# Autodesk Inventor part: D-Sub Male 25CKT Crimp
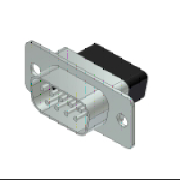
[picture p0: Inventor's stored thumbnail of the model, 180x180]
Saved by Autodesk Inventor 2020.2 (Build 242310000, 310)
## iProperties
Manager: www.cadconsulting.pl
Company: Fabian Stasiak CAD Consulting
IsCustomPart: 0
GlobalPropertyList: <PropertyList/>
Created: 2014-02
Part Number: D-Sub Male 25CKT Crimp
Material: Ogólny
Description: Wtyczka, złącze D-Sub
Document SubType Name: Modeling
Designer: F.Stasiak
Language: pl-PL
Size Designation: D-Sub Male Crimp 25CKT
Categories: <MemberInstance><Categories><Category DisplayName="Kable i wiązki przewodów" InternalName="e4a7e005-5e42-4d16-b293-125e7f0d0512" Mnemonic="CABLEANDHARNESS"><Cat
Density: 1 g/cm^3
Appearance: Domyślna
Catalog Web Link: www.expertbooks.pl
Author: F.Stasiak
Subject: Zbiór ćwiczeń. Autodesk Inventor 2020. Kurs Professional
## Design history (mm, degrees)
sketch "Sketch1"
  geometry: L1 (24.943, 6.299)-(-24.943, 6.299); L2 (-24.943, -6.299)-(24.943, -6.299); L3 (26.518, -4.724)-(26.518, 4.724); L4 (-26.518, 4.724)-(-26.518, -4.724); L5 (0, 6.299)-(0, -6.299); L6 (-23.52, 0)-(23.52, 0); L7 (26.518, 4.724)-(24.943, 4.724); L8 (24.943, 4.724)-(24.943, 6.299); L9 (26.518, -4.724)-(24.943, -4.724); L10 (24.943, -4.724)-(24.943, -6.299); L11 (-24.943, 6.299)-(-24.943, 4.724); L12 (-24.943, 4.724)-(-26.518, 4.724); L13 (-26.518, -4.724)-(-24.943, -4.724); L14 (-24.943, -4.724)-(-24.943, -6.299); C1 r 1.524 at (-23.52, 0); C2 r 1.524 at (23.52, 0); A1 r 1.575 centre (24.943, 4.724) between (26.518, 4.724) and (24.943, 6.299); A2 r 1.575 centre (24.943, -4.724) between (24.943, -6.299) and (26.518, -4.724); A3 r 1.575 centre (-24.943, 4.724) between (-24.943, 6.299) and (-26.518, 4.724); A4 r 1.575 centre (-24.943, -4.724) between (-26.518, -4.724) and (-24.943, -6.299); 7 further points
  constraints: 28 end point, 8 point on circle, 6 centre point, 6 midpoint, 5 perpendicular, 4 horizontal alignment, 4 vertical alignment, 3 equal radius, 3 parallel, 1 coincident
  dimensions: "d124" = 53.0352 distance between parallel lines of L3 L4 (derived); "d125" = 12.5984 distance between parallel lines of L2 L1; "d126" = 1.5748 radius of A1; "d134" = 3.048 diameter of C1; "d135" = 47.0408 distance of L6.start L6.end (derived)
extrude "Wyciągnięcie1" new body sketch "Sketch1" stored distance "d4" = 0.762; taper "d5" = 0 deg
sketch "Sketch2"
  geometry: L1 (-24.943, 6.299)-(24.943, 6.299) reference; L2 (24.943, -6.299)-(-24.943, -6.299) reference; L3 (-16.153, -3.95)-(16.153, -3.95); L4 (16.65, 3.95)-(-16.65, 3.95); L5 (-19.151, 0.969)-(-18.654, -1.851); L6 (18.654, -1.851)-(19.151, 0.969); L7 (0, 3.95)-(0, -3.95); L8 (-19.19, 6.299)-(-19.19, -6.299); L9 (19.19, 6.299)-(19.19, -6.299); L10 (26.518, 4.724)-(26.518, -4.724) reference; L11 (-16.65, 4.356)-(16.65, 4.356); L12 (-16.153, -4.356)-(16.153, -4.356); L13 (-19.551, 0.898)-(-19.054, -1.921); L14 (19.551, 0.898)-(19.054, -1.921); A1 r 2.54 centre (-16.65, 1.41) between (-16.65, 3.95) and (-19.151, 0.969); A2 r 2.54 centre (-16.153, -1.41) between (-18.654, -1.851) and (-16.153, -3.95); A3 r 2.54 centre (16.153, -1.41) between (16.153, -3.95) and (18.654, -1.851); A4 r 2.54 centre (16.65, 1.41) between (19.151, 0.969) and (16.65, 3.95); A5 r 2.946 centre (-16.65, 1.41) between (-16.65, 4.356) and (-19.551, 0.898); A6 r 2.946 centre (16.153, -1.41) between (16.153, -4.356) and (19.054, -1.921); A7 r 2.946 centre (16.65, 1.41) between (19.551, 0.898) and (16.65, 4.356); A8 r 2.946 centre (-16.153, -1.41) between (-19.054, -1.921) and (-16.153, -4.356); 7 further points
  constraints: 22 end point, 16 point on circle, 8 centre point, 7 tangent, 6 midpoint, 4 coincident, 4 point on line, 3 equal radius, 3 parallel, 3 perpendicular, 2 vertical alignment, 1 horizontal alignment
  dimensions: "d127" = 2.54 radius of A4; "d129" = 7.8994 distance between parallel lines of L3 L4; "d131" = 10 deg angle of L7 L5; "d132" = 10 deg angle of L6 L7; "d133" = 38.3794 distance between parallel lines of L9 L8 (derived); "d198" = 0.49714 horizontal distance of A2.centre A1.centre; "d199" = 2.8194 vertical distance of A2.centre A1.centre; "d200" = 0.49714 horizontal distance of A3.centre A4.centre; "d201" = 2.8194 vertical distance of A3.centre A4.centre; "d292" = 0.4064 radial gap between concentric circles of A1 A5; "d293" = 0.4064 distance between parallel lines of L11 L4 (derived); "d294" = 0.4064 distance between parallel lines of L3 L12 (derived)
extrude "Wyciągnięcie2" join sketch "Sketch2" distance "d9" = 5.5372; taper "d10" = 0 deg
sketch "Sketch3"
  geometry: L1 (-20.61, 3.651)-(-19.226, -4.198); L2 (-17.676, -5.499)-(17.676, -5.499); L3 (19.059, 5.499)-(-19.059, 5.499); L4 (19.226, -4.198)-(20.586, 3.512); L5 (0, 5.499)-(0, -5.499); L6 (-20.634, 6.274)-(-20.634, -6.274); L7 (20.641, 6.274)-(20.641, -6.274); L8 (-24.943, 6.299)-(24.943, 6.299) reference; L9 (-26.518, -4.724)-(-26.518, 4.724) reference; L10 (24.943, -6.299)-(-24.943, -6.299) reference; L11 (-19.059, 5.499)-(-19.059, 3.924); L12 (-19.059, 3.924)-(-20.61, 3.651); L13 (-19.226, -4.198)-(-17.676, -3.924); L14 (-17.676, -3.924)-(-17.676, -5.499); L15 (17.676, -3.924)-(17.676, -5.499); L16 (17.676, -3.924)-(19.226, -4.198); L17 (19.059, 5.499)-(19.066, 3.924); L18 (19.066, 3.924)-(20.586, 3.512); L19 (26.518, 4.724)-(26.518, -4.724) reference; A1 r 1.575 centre (-17.676, -3.924) between (-19.226, -4.198) and (-17.676, -5.499); A2 r 1.575 centre (-19.059, 3.924) between (-19.059, 5.499) and (-20.61, 3.651); A3 r 1.575 centre (17.676, -3.924) between (17.676, -5.499) and (19.226, -4.198); A4 r 1.575 centre (19.066, 3.924) between (20.586, 3.512) and (19.059, 5.499); 5 further points
  constraints: 30 end point, 8 point on circle, 5 midpoint, 4 centre point, 4 parallel, 3 equal radius, 3 perpendicular, 2 horizontal alignment, 2 tangent, 2 vertical alignment
  dimensions: "d114" = 10.9982 distance between parallel lines of L2 L3; "d119" = 1.5748 radius of A4; "d120" = 10 deg angle of L5 L1; "d121" = 10 deg angle of L4 L5; "d122" = 41.275 distance between parallel lines of L7 L6 (derived); "d204" = 90 deg angle of L3 L11; "d205" = 100 deg angle of L11 L12; "d206" = 90 deg angle of L2 L14 (derived); "d207" = 80 deg angle of L14 L13 (derived); "d208" = 90 deg angle of L2 L15 (derived); "d209" = 80 deg angle of L16 L15 (derived); "d210" = 105.42 deg angle of L17 L18 (derived); "d211" = 90.2379 deg angle of L3 L17 (derived); "d295" = 1.38392 horizontal distance of L13.end L11.end; "d296" = 1.39046 horizontal distance of L15.start L17.end
extrude "Wyciągnięcie3" join sketch "Sketch3" distance "d14" = 3.937; taper "d15" = 0 deg
sketch "Sketch4"
  geometry: L1 (-19.059, 5.499)-(19.059, 5.499) reference; L2 (18.046, -2.574)-(18.879, 2.15); L3 (-16.845, -3.581)-(16.845, -3.581); L4 (17.678, 3.581)-(-17.678, 3.581); L5 (-18.879, 2.15)-(-18.046, -2.574); L6 (0, 3.581)-(0, -3.581); L7 (26.518, 4.724)-(26.518, -4.724) reference; L8 (-24.943, 6.299)-(24.943, 6.299) reference; L9 (-26.518, -4.724)-(-26.518, 4.724) reference; L10 (24.943, -6.299)-(-24.943, -6.299) reference; L11 (-18.898, 6.299)-(-18.898, -6.299); L12 (18.898, 6.299)-(18.898, -6.299); L13 (-19.226, -4.198)-(-20.61, 3.651) reference; L14 (17.676, -5.499)-(-17.676, -5.499) reference; L15 (-17.678, 2.362)-(-17.678, 3.581); L16 (-17.678, 2.362)-(-18.879, 2.15); L17 (-16.845, -2.362)-(-16.845, -3.581); L18 (-16.845, -2.362)-(-18.046, -2.574); L19 (16.845, -2.362)-(18.046, -2.574); L20 (16.845, -2.362)-(16.845, -3.581); L21 (17.678, 3.581)-(17.678, 2.362); L22 (17.678, 2.362)-(18.879, 2.15); C1 r 1.524 at (-23.52, 0) reference; C2 r 1.524 at (23.52, 0) reference; A1 r 1.219 centre (16.845, -2.362) between (16.845, -3.581) and (18.046, -2.574); A2 r 1.219 centre (17.678, 2.362) between (18.879, 2.15) and (17.678, 3.581); A3 r 1.219 centre (-16.845, -2.362) between (-18.046, -2.574) and (-16.845, -3.581); A4 r 1.219 centre (-17.678, 2.362) between (-17.678, 3.581) and (-18.879, 2.15); A5 r 1.575 centre (24.943, 4.724) between (26.518, 4.724) and (24.943, 6.299) reference; A6 r 1.575 centre (-24.943, 4.724) between (-24.943, 6.299) and (-26.518, 4.724) reference; A7 r 1.575 centre (-24.943, -4.724) between (-26.518, -4.724) and (-24.943, -6.299) reference; A8 r 1.575 centre (24.943, -4.724) between (24.943, -6.299) and (26.518, -4.724) reference; 3 further points
  constraints: 30 end point, 8 point on circle, 6 parallel, 5 perpendicular, 4 centre point, 4 midpoint, 4 point on line, 3 equal radius, 2 tangent, 1 horizontal alignment, 1 vertical alignment
  dimensions: "d136" = 7.1628 distance between parallel lines of L3 L4; "d137" = 1.2192 radius of A2; "d139" = 10 deg angle of L6 L5; "d140" = 10 deg angle of L2 L6; "d141" = 37.7952 distance between parallel lines of L12 L11 (derived); "d212" = 90 deg angle of L4 L15; "d213" = 100 deg angle of L16 L15 (derived); "d214" = 90 deg angle of L3 L17 (derived); "d215" = 80 deg angle of L17 L18 (derived); "d216" = 90 deg angle of L3 L20 (derived); "d217" = 80 deg angle of L19 L20; "d218" = 90 deg angle of L4 L21 (derived); "d219" = 100 deg angle of L22 L21 (derived)
extrude "Wyciągnięcie4" join sketch "Sketch4" distance "d19" = 7.1882; taper "d20" = 0 deg
sketch "Sketch14"
  geometry: L1 (16.659, 3.404)-(16.659, 2.642); L2 (16.659, 2.642)-(16.564, 2.642); L3 (16.564, 2.642)-(16.564, 3.274); L4 (16.469, 3.16)-(16.469, 3.29); L5 (16.564, 3.404)-(16.659, 3.404); L6 (16.469, 3.29)-(16.564, 3.404); L7 (16.564, 3.274)-(16.469, 3.16); C1 r 1.105 at (16.612, 1.422); C2 r 1.105 at (15.245, -1.422); A1 r 1.219 centre (16.845, -2.362) between (16.845, -3.581) and (18.046, -2.574) reference; A2 r 1.219 centre (17.678, 2.362) between (18.879, 2.15) and (17.678, 3.581) reference; 1 further point
  constraints: 14 end point, 2 centre point, 1 midpoint, 1 vertical alignment
  dimensions: "d144" = 2.2098 diameter of C1; "d162" = 2.2098 diameter of C2; "d181" = 0.09525 distance of L1.end L2.end; "d182" = 40.0062 deg angle of L3 L7; "d183" = 0.1297 distance of L4.start L4.end; "d184" = 0.09525 distance of L5.start L1.start; "d185" = 0.762 distance of L1.start L1.end; "d186" = 0.6323 distance of L2.end L3.end; "d187" = 0.14816 distance of L4.end L5.start; "d188" = 0.14816 distance of L3.end L4.start; "d189" = 40.0062 deg angle of L4 L7; "d190" = 139.994 deg angle of L4 L6; "d297" = 1.0668 horizontal distance of A2.centre C1.centre; "d298" = 0.9398 vertical distance of C1.centre A2.centre; "d299" = 1.6002 horizontal distance of A1.centre C2.centre; "d300" = 0.9398 vertical distance of A1.centre C2.centre
sketch "Sketch15"
  geometry: C1 r 0.533 at (-16.612, 1.422); C2 r 0.533 at (-15.24, -1.422); A1 r 2.54 centre (16.65, 1.41) between (19.151, 0.969) and (16.65, 3.95); A2 r 2.54 centre (16.153, -1.41) between (16.153, -3.95) and (18.654, -1.851); A3 r 2.54 centre (-16.65, 1.41) between (-16.65, 3.95) and (-19.151, 0.969) reference; A4 r 2.54 centre (-16.153, -1.41) between (-18.654, -1.851) and (-16.153, -3.95) reference
  constraints: 4 centre point, 4 point on circle, 1 equal radius
  dimensions: "d149" = 1.0668 diameter of C1; "d301" = 0.0381 horizontal distance of A3.centre C1.centre; "d302" = 0.0127 vertical distance of A3.centre C1.centre; "d303" = 0.91256 horizontal distance of A4.centre C2.centre; "d304" = 0.0127 vertical distance of A4.centre C2.centre
pattern_linear "Wzór prostokątny7" dims "d159" = 2.7432 (derived)
pattern_linear "Wzór prostokątny8" dims "d178" = 2.7432 (derived)
sketch "Sketch16"
  geometry: L1 (16.659, 2.642)-(16.564, 2.642) reference; L2 (16.564, 2.642)-(16.564, 3.274) reference; L3 (16.564, 3.274)-(16.469, 3.16) reference; L4 (16.469, 3.16)-(16.469, 3.29) reference; L5 (16.469, 3.29)-(16.564, 3.404) reference; L6 (16.564, 3.404)-(16.659, 3.404) reference; L7 (16.659, 3.404)-(16.659, 2.642) reference; L8 (16.845, -3.581)-(-16.845, -3.581) reference; L9 (18.879, 2.15)-(18.046, -2.574) reference; L10 (-17.678, 3.581)-(17.678, 3.581) reference; L11 (-18.046, -2.574)-(-18.879, 2.15) reference; L12 (16.845, -3.581)-(-16.845, -3.581) reference; L13 (18.879, 2.15)-(18.046, -2.574) reference; L14 (-17.678, 3.581)-(17.678, 3.581) reference; L15 (-18.046, -2.574)-(-18.879, 2.15) reference; A1 r 1.219 centre (-17.678, 2.362) between (-17.678, 3.581) and (-18.879, 2.15) reference; A2 r 1.219 centre (16.845, -2.362) between (16.845, -3.581) and (18.046, -2.574) reference; A3 r 1.219 centre (17.678, 2.362) between (18.879, 2.15) and (17.678, 3.581) reference; A4 r 1.219 centre (-16.845, -2.362) between (-18.046, -2.574) and (-16.845, -3.581) reference; A5 r 1.219 centre (16.845, -2.362) between (16.845, -3.581) and (18.046, -2.574) reference; A6 r 1.219 centre (17.678, 2.362) between (18.879, 2.15) and (17.678, 3.581) reference; A7 r 1.219 centre (-16.845, -2.362) between (-18.046, -2.574) and (-16.845, -3.581) reference; 37 further points
  dimensions: "P1C" = 1.0668 horizontal distance of A3.centre point (16.612, 1.422); "P1R" = 0.9398 vertical distance of A3.centre point (16.612, 1.422); "P2C" = 3.81 horizontal distance of A3.centre point (13.868, 1.422); "P2R" = 0.9398 vertical distance of A3.centre point (13.868, 1.422); "P3C" = 6.5532 horizontal distance of A6.centre point (11.125, 1.422); "P3R" = 0.9398 vertical distance of A3.centre point (11.125, 1.422); "P4C" = 9.2964 horizontal distance of A6.centre point (8.382, 1.422); "P4R" = 0.9398 vertical distance of A3.centre point (8.382, 1.422); "P5C" = 12.0396 horizontal distance of A3.centre point (5.639, 1.422); "P5R" = 0.9398 vertical distance of A6.centre point (5.639, 1.422); "P6C" = 14.7828 horizontal distance of A3.centre point (2.896, 1.422); "P6R" = 0.9398 vertical distance of A3.centre point (2.896, 1.422); "P7C" = 17.526 horizontal distance of A3.centre point (0.152, 1.422); "P7R" = 0.9398 vertical distance of A3.centre point (0.152, 1.422); "P8C" = 20.2692 horizontal distance of A3.centre point (-2.591, 1.422); "P8R" = 0.9398 vertical distance of A3.centre point (-2.591, 1.422); "P9C" = 23.0124 horizontal distance of A6.centre point (-5.334, 1.422); "P9R" = 0.9398 vertical distance of A3.centre point (-5.334, 1.422); "P10C" = 25.7556 horizontal distance of A6.centre point (-8.077, 1.422); "P10R" = 0.9398 vertical distance of A3.centre point (-8.077, 1.422); "P11C" = 28.4988 horizontal distance of A6.centre point (-10.82, 1.422); "P11R" = 0.9398 vertical distance of A3.centre point (-10.82, 1.422); "P12C" = 31.242 horizontal distance of A3.centre point (-13.564, 1.422); "P12R" = 0.9398 vertical distance of A3.centre point (-13.564, 1.422); "P13C" = 33.9852 horizontal distance of A3.centre point (-16.307, 1.422); "P13R" = 0.9398 vertical distance of A3.centre point (-16.307, 1.422); "P14C" = 2.4384 horizontal distance of A3.centre point (15.24, -1.422); "P14R" = 3.7846 vertical distance of A3.centre point (15.24, -1.422); "P15C" = 5.1816 horizontal distance of A3.centre point (12.497, -1.422); "P15R" = 3.7846 vertical distance of A3.centre point (12.497, -1.422); "P16C" = 7.9248 horizontal distance of A3.centre point (9.754, -1.422); "P16R" = 3.7846 vertical distance of A3.centre point (9.754, -1.422); "P17C" = 10.668 horizontal distance of A3.centre point (7.01, -1.422); "P17R" = 3.7846 vertical distance of A3.centre point (7.01, -1.422); "P18C" = 13.4112 horizontal distance of A3.centre point (4.267, -1.422); "P18R" = 3.7846 vertical distance of A6.centre point (4.267, -1.422); "P19C" = 16.1544 horizontal distance of A3.centre point (1.524, -1.422); "P19R" = 3.7846 vertical distance of A3.centre point (1.524, -1.422); "P20C" = 18.8976 horizontal distance of point (-1.219, -1.422) A3.centre; "P20R" = 3.7846 vertical distance of A3.centre point (-1.219, -1.422); "P21C" = 21.6408 horizontal distance of A6.centre point (-3.962, -1.422); "P21R" = 3.7846 vertical distance of A3.centre point (-3.962, -1.422); "P22C" = 24.384 horizontal distance of A3.centre point (-6.706, -1.422); "P22R" = 3.7846 vertical distance of A3.centre point (-6.706, -1.422); "P23C" = 27.1272 horizontal distance of A3.centre point (-9.449, -1.422); "P23R" = 3.7846 vertical distance of A3.centre point (-9.449, -1.422); "P24C" = 29.8704 horizontal distance of A3.centre point (-12.192, -1.422); "P24R" = 3.7846 vertical distance of A3.centre point (-12.192, -1.422); "P25C" = 32.6136 horizontal distance of A6.centre point (-14.935, -1.422); "P25R" = 3.7846 vertical distance of A3.centre point (-14.935, -1.422); "P26C" = 0.254 horizontal distance of A3.centre point (17.424, 2.108); "P26R" = 0.254 horizontal distance of A3.centre point (17.424, 2.108); "P27C" = 0.254 horizontal distance of A3.centre point (17.424, 2.108); "P27R" = 0.254 horizontal distance of A3.centre point (17.424, 2.108); "P28C" = 0.254 horizontal distance of A3.centre point (17.424, 2.108); "P28R" = 0.254 horizontal distance of A3.centre point (17.424, 2.108); "P29C" = 0.254 horizontal distance of A3.centre point (17.424, 2.108); "P29R" = 0.254 horizontal distance of A3.centre point (17.424, 2.108); "P30C" = 0.254 horizontal distance of A3.centre point (17.424, 2.108); "P30R" = 0.254 horizontal distance of A3.centre point (17.424, 2.108); "P31C" = 0.254 horizontal distance of A3.centre point (17.424, 2.108); "P31R" = 0.254 horizontal distance of A3.centre point (17.424, 2.108); "P32C" = 0.254 horizontal distance of A3.centre point (17.424, 2.108); "P32R" = 0.254 horizontal distance of A3.centre point (17.424, 2.108)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
node "1"
node "2"
node "3"
node "4"
node "5"
node "6"
node "7"
node "8"
node "9"
node "10"
node "11"
node "12"
node "13"
node "14"
node "15"
node "16"
node "17"
node "18"
node "19"
node "20"
node "21"
node "22"
node "23"
node "24"
node "25"
body "Solid1"
extrude "Wyciągnięcie proste15" cut sketch "Sketch14" stored distance "d147" = 25.4; taper "d148" = 0 deg
extrude "Wyciągnięcie proste16" join sketch "Sketch15" distance "d152" = 5.08; taper "d153" = 0 deg
extrude "Wyciągnięcie proste17" cut sketch "Sketch14" stored distance "d165" = 25.4; taper "d166" = 0 deg
extrude "Wyciągnięcie proste18" join sketch "Sketch15" distance "d171" = 5.08; taper "d172" = 0 deg
extrude "Wyciągnięcie proste19" join sketch "Sketch14" distance "d193" = 0.0254; taper "d194" = 0 deg
node "Projected Loop2"
other parameters: "DimA" = 53.0352 [user parameter], "DimB" = 47.0408 [user parameter], "DimC" = 38.3794 [user parameter], "DimD" = 41.275 [user parameter], "DimE" = 37.7952 [user parameter], "PinPitch" = 2.7432 [user parameter]
